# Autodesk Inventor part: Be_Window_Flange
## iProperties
Shininess: 64.0
Length Units: 11269
Angle Units: 11279
Time Units: 11290
Mass Units: 11283
Length Display Precision: 3
Angle Display Precision: 2
Compacted: True
Part Number: Be_Window_Flange
Document SubType Name: Modeling
Created: 2004-07
Designer: John Blackburn
Manufacturer: Standard
Standards Organization: Custom
Project: Mucap
Material: Stainless Steel, Austenitic
Description: Mucap, Beryllium Window Flange
Density: 0.0
Volumn: 0.0
Area: 0.0
PropertySet Name: Model Information
Control State: 0
Master: False
Checked Out: False
Author: John Blackburn
Title: Mucap, Beryllium Window Flange
Subject: mucap
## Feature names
1. Extrusion1
2. Hole1
3. Circular Pattern1
4. Chamfer1
5. Extrusion2
